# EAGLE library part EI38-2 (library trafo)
TRANSFORMER 1 primary winding, 2 secondary windings ERA
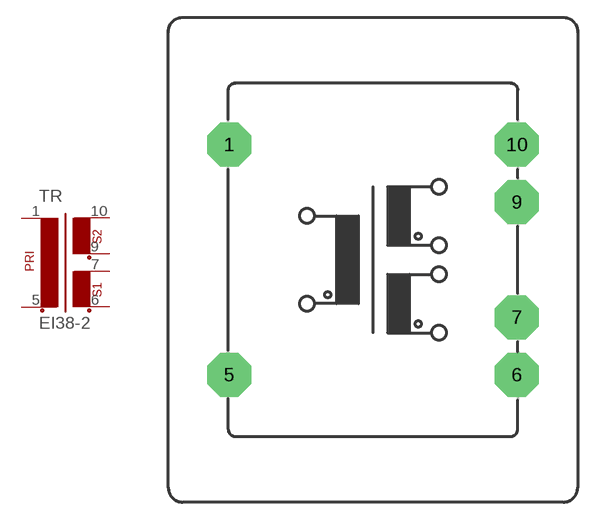
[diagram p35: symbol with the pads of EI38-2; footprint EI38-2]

Designator prefix TR

## EI38-2  [EI38-2]
1  1  pas
5  2  pas
6  3  pas
7  4  pas
9  5  pas
10  6  pas

## Footprint EI38-2 (pad centres in mm)
TRANSFORMER 1 primary winding, 2 secondary windings
drill 1.118 pad 3.81 octagon: 1 -12.497,10.008; 5 -12.497,-10.008; 6 12.497,-10.008; 7 12.497,-5.004; 9 12.497,5.004; 10 12.497,10.008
